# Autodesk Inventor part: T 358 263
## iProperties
Created: 2006-09
Part Number: T 358 263
Material: 2.0402
Document SubType Name: Modeling
Designer: I.Baliuc
Manufacturer: Standard
Standards Organization: Custom
Description: Buchse
Density: 8.2 g/cm^3
Title: Buchse
Company: Mayer & Müller AG Schaltgeräte
Abmessung: Rd 20
HalbzeugNorm: DIN 1756
Author: T.Messerschmitt
Revision Number: 358263
Keywords: 267038
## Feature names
1. Drehung1 [Revolution]
